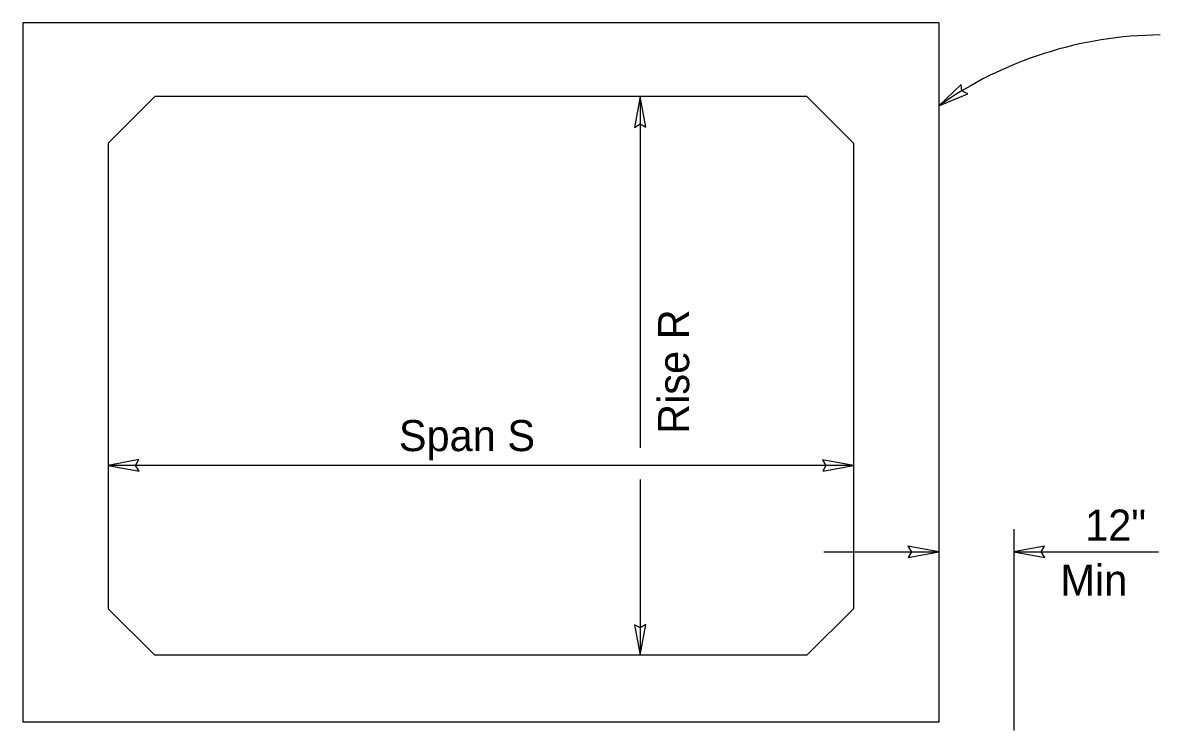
# Model space of a CAD drawing. Extents: x 0 to 2.83, y -0.03 to 1.83.
# Drawn here: x 1.2084 to 1.6855, y 0.2105 to 0.5038 of the extents above; entities that cross this region are included whole.
import ezdxf

# ---------------------------------------------------------------- set-up
doc = ezdxf.new("R2010")
doc.units = 0
for name, color, linetype in [('50', 7, 'Continuous'), ('54', 7, 'Continuous'), ('55', 7, 'Continuous'), ('57', 7, 'Continuous')]:
    doc.layers.add(name, color=color, linetype=linetype)

msp = doc.modelspace()

# ---------------------------------------------------------------- linework, layer by layer
at = {"layer": '50'}
for p, q in [((1.2084472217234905, 0.5038340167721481), (1.20844722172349, 0.21053974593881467)), ((1.5925618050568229, 0.5038340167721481), (1.2084472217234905, 0.5038340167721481)), ((1.5925618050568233, 0.5038340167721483), (1.5925618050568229, 0.21053974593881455)), ((1.2442545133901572, 0.4533782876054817), (1.2637857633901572, 0.4729095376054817)), ((1.5372232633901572, 0.4729095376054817), (1.2637857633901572, 0.4729095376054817)), ((1.5567545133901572, 0.4533782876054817), (1.5372232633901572, 0.4729095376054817)), ((1.2442545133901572, 0.4533782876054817), (1.2442545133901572, 0.2580657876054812)), ((1.5567545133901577, 0.4533782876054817), (1.5567545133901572, 0.2580657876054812)), ((1.2637857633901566, 0.2385345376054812), (1.2442545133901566, 0.2580657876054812)), ((1.5372232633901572, 0.2385345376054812), (1.5567545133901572, 0.2580657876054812)), ((1.5372232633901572, 0.2385345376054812), (1.2637857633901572, 0.2385345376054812)), ((1.5925618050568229, 0.21053974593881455), (1.20844722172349, 0.21053974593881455))]:
    msp.add_line(p, q, dxfattribs=at)
at = {"layer": '54'}
for points in [[(1.5925618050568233, 0.4689503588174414), (1.6047454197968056, 0.47404776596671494), (1.6021856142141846, 0.4752152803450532), (1.6020146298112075, 0.47796770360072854)], [(1.4673177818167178, 0.4729095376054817), (1.4649427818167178, 0.45991787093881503), (1.4673177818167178, 0.46142620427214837), (1.4697177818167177, 0.46006787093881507)], [(1.2442545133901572, 0.31819234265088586), (1.2572461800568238, 0.3158173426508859), (1.2557378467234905, 0.31819234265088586), (1.2570961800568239, 0.3205923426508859)], [(1.5567545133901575, 0.31819234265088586), (1.5437628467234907, 0.3205673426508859), (1.545271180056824, 0.31819234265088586), (1.5439128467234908, 0.3157923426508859)], [(1.5925618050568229, 0.2819393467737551), (1.5795701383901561, 0.2843143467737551), (1.5810784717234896, 0.2819393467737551), (1.5797201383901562, 0.27953934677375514)], [(1.6240283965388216, 0.2819393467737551), (1.6370200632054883, 0.27956434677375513), (1.635511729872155, 0.2819393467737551), (1.6368700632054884, 0.2843393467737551)], [(1.4673177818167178, 0.2385345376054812), (1.4696927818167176, 0.2515262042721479), (1.4673177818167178, 0.25001787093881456), (1.4649177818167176, 0.2513762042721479)]]:
    msp.add_lwpolyline(points, close=True, dxfattribs=at)
at = {"layer": '55'}
for p, q in [((1.4673177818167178, 0.4729095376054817), (1.4673177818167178, 0.3255971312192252)), ((1.5567545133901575, 0.31819234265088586), (1.2442545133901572, 0.31819234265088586)), ((1.4673177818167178, 0.3123214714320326), (1.4673177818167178, 0.2385345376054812)), ((1.6240283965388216, 0.2914674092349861), (1.6240283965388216, 0.20698561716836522)), ((1.544412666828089, 0.2819393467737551), (1.5925618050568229, 0.2819393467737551)), ((1.6240283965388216, 0.2819393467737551), (1.6847663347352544, 0.2819393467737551))]:
    msp.add_line(p, q, dxfattribs=at)
msp.add_arc((1.6865389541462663, 0.33543443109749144), 0.16327341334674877, 90.38071637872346, 125.14036213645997, dxfattribs=at)

# ---------------------------------------------------------------- texts
at = {"layer": '57'}
msp.add_text('Rise R', height=0.013020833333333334, rotation=90, dxfattribs=at).set_placement((1.4878962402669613, 0.3313949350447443))
for s, p in [('Span S', (1.366161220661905, 0.32417473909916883)), ('12"', (1.6539467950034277, 0.2866393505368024)), ('Min', (1.6435788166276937, 0.2635493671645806))]:
    msp.add_text(s, height=0.013020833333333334, dxfattribs=at).set_placement(p)

doc.saveas('drawing.dxf')
